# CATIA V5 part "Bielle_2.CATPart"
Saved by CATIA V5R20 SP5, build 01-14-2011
Part number: Bielle_2
Bounding box of the stored display mesh (mm): x -32.173 to -8.443, y -34.702 to 76.085, z 9 to 12
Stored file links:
  D:\thinkmotion-MPB\Dropbox\IAO_2011\MMS_GR3\IAO_2011_1523_mkessler\mkessler\mkessler_IAO\mkessler_INIT\Bielle_2.CATPart
  C:\Users\MARLENE\Documents\IFMA\S3\IAO\Copie de CAO\Assemblage_final.CATProduct
  D:\thinkmotion-MPB\Dropbox\IAO_2011\MMS_GR3\IAO_2011_1523_mkessler\mkessler\mkessler_IAO\mkessler_INIT\Squelette_bielle_1.CATPart
  D:\thinkmotion-MPB\Dropbox\IAO_2011\MMS_GR3\IAO_2011_1523_mkessler\mkessler\mkessler_IAO\mkessler_INIT\Squelette_bielle_2.CATPart
  D:\thinkmotion-MPB\Dropbox\IAO_2011\MMS_GR3\IAO_2011_1523_mkessler\mkessler\mkessler_IAO\mkessler_INIT\Squelette_bielle_3.CATPart
  D:\thinkmotion-MPB\Dropbox\IAO_2011\MMS_GR3\IAO_2011_1523_mkessler\mkessler\mkessler_IAO\mkessler_INIT\Bielle_1.CATPart
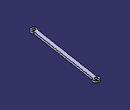
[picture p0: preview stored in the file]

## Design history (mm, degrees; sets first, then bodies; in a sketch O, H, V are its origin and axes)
External parameters (linked from other documents)
  External.Diametre_bielle_ext = 8 mm
  External.Diametre_bielle_int = 4 mm
  External.Largeur_bielle = 5 mm
  External.Longueur_bielle = 104 mm
Set1
  Plane1: linked copy from another document
  Point1: linked copy from another document
  Point2: linked copy from another document
  Line1: linked copy from another document
Body1 (main body)
  Sketch1 on Plane1, origin (0, 0, 9), H (1, 0, 0), V (0, 1, 0)
    circle A1 centre (-28.18, -30.709) radius 2
    arc A2 centre (-28.18, -30.709) radius 4 from (-30.1785, -27.244) to (-25.2361, -28.001) ccw
    circle A3 centre (-12.4355, 72.0923) radius 2
    arc A4 centre (-12.4355, 72.0923) radius 4 from (-10.4371, 68.6273) to (-15.3794, 69.3843) ccw
    reference projected point E1 (-12.4355, 72.0923) from Point1
    reference projected point E2 (-12.4355, 72.0923) from Point1
    reference projected point E3 (-28.18, -30.709) from Point2
    reference projected point E4 (-28.18, -30.709) from Point2
    line L1 (-10.4371, 68.6273) -> (-25.2361, -28.001)
    line L2 (-15.3794, 69.3843) -> (-30.1785, -27.244)
    reference projected line E5 (-12.4355, 72.0923) -> (-28.18, -30.709) from Line1
    radius A4 = 4
    radius A2 = 4
    radius A1 = 2
    radius A3 = 2
    distance L2 L1 = 5
    concentricity: A4 E1, A3 E2, E3 A2, E4 A1
    symmetry: L2 L1 E5
  Pad1: profile Sketch1, direction (0, 0, 1), length 3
